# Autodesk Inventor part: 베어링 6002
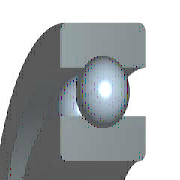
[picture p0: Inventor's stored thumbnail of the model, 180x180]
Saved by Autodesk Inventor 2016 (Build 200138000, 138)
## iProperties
Created: 2012-02
Part Number: 베어링 6002
Material: 강철, 연강
Description: 깊은 그루브 볼 베어링
Document SubType Name: Modeling
Standard: KS B 2023
Designer: mduedu
Standards Organization: KS
Language: ko-KR
Size Designation: 6002 - 15 x 32 x 9
Categories: <MemberInstance><Categories><Category DisplayName="샤프트 부품" InternalName="7f7aeb1f-a693-4053-b835-cee3144e0d98" Mnemonic="SHFT"><Category DisplayName="베어링" Inter
Density: 1 g/cm^3
Appearance: 노란색
IsCustomPart: 1
Author: mduedu
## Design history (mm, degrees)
sketch "스케치" dims "d0" = 4.42 (= -0.26 x WD + 0.26 x BD)
  geometry: L1 (2.29, 11.75)-(6.71, 11.75); L2 (4.5, 11.75)-(4.5, 9.54); L3 (4.5, 11.75)-(4.5, 13.96); L4 (2.858, 10.271)-(0, 10.271); L5 (0, 7.5)-(9, 7.5); L6 (2.858, 13.229)-(0, 13.229); L7 (0, 16)-(9, 16); L8 (9, 7.5)-(9, 10.271); L9 (6.142, 10.271)-(9, 10.271); L10 (6.142, 13.229)-(9, 13.229); L11 (9, 16)-(9, 13.229); L12 (-1.4, 0)-(8.4, 0) reference; L13 (0, -0.3)-(0, 5.3) reference
  constraints: 22 end point, 4 point on line, 2 collinear, 2 perpendicular, 2 symmetric about line, 1 midpoint, 1 parallel, 14 other
  dimensions: "d9" = 15 diameter of L5 L12 (= WD); "d11" = 32 diameter of L7 L12 (= BD); "d12" = 9 distance between parallel lines of L8 L13 (= KB); "d13" = 20.542 diameter of L9 L12 (= 0.326 x BD + 0.674 x WD)
revolve "본체" stored, may be unused: angle "d6" = 90 deg
revolve "볼" stored, may be unused: angle "d7" = 90 deg
pattern_circular "IDS_ARRAYBALL[SIMPL:T]" dims angle "d3" = 360 deg
body "Solid1"
fillet "모깎기1" dims "d1" = 0.3 (= KRS)
other parameters: "WD" = 15 [user parameter; used in 5 equation terms], "BD" = 32 [user parameter; used in 5 equation terms], "KB" = 9 [user parameter; used in 1 equation term], "KRS" = 0.3 [user parameter; used in 1 equation term], "d4" = 0, "d5" = 0, "d8" = 0, "d14" = 0, "d15" = 0, "BBA" = 0 [user parameter], "BC0" = 2850000 [user parameter], "BC" = 5590000 [user parameter], "BR" = 16 (= 0.5 x BD) [user parameter], "WR" = 7.5 (= 0.5 x WD) [user parameter]
